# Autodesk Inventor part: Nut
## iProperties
Shininess: 77.0
Length Units: 11269
Angle Units: 11279
Time Units: 11290
Mass Units: 11283
Length Display Precision: 3
Angle Display Precision: 2
Created: 2002-02
Part Number: Nut
Document SubType Name: Modeling
Designer: ***
Density: 0.0
Volumn: 0.0
Area: 0.0
PropertySet Name: Model Information
Control State: 0
Master: False
Checked Out: False
Author: ***
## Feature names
1. Extrusion1
2. Fillet1
3. Extrusion2
4. Hole1
